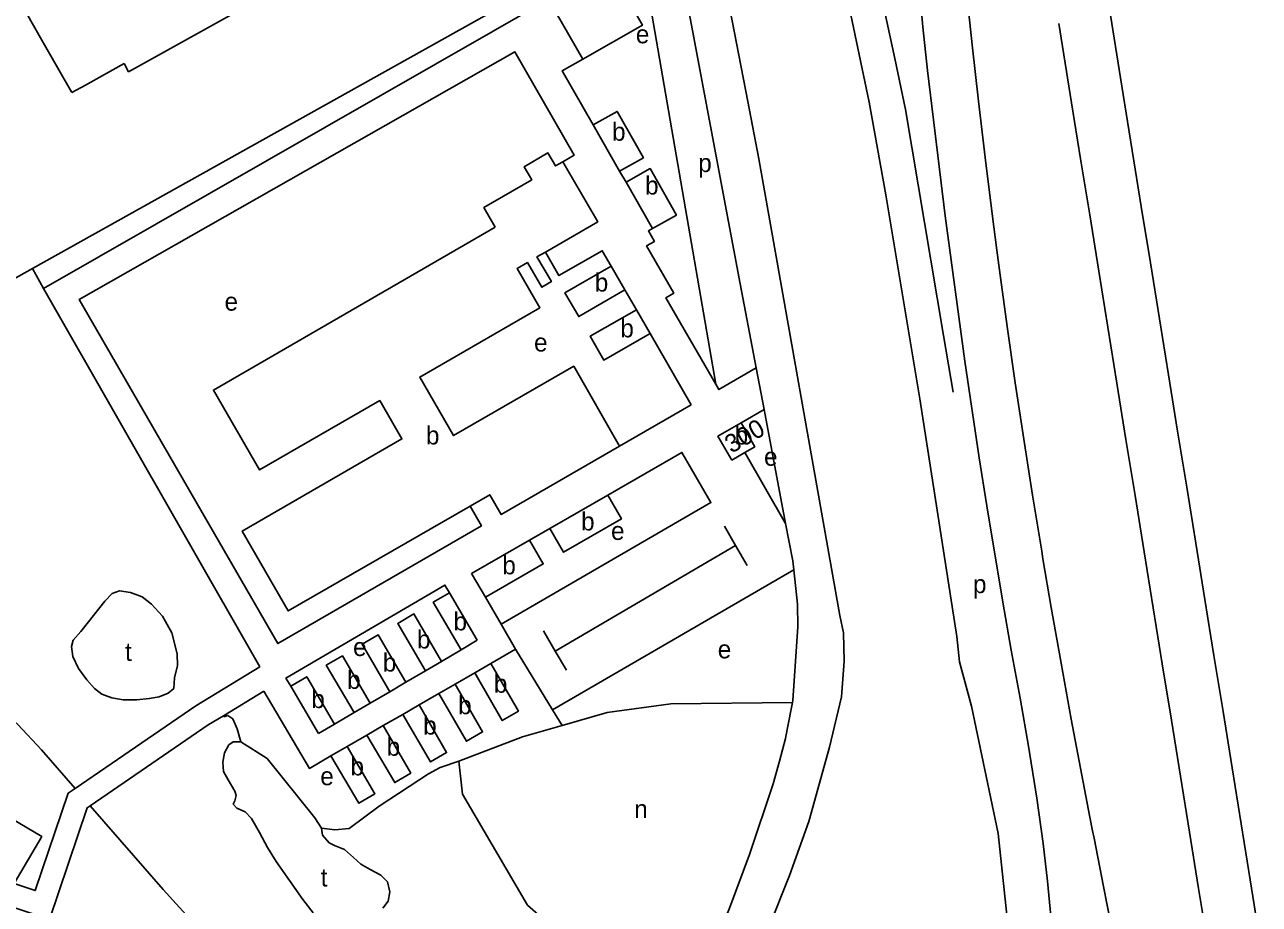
# Model space of a CAD drawing. Extents: x 155696 to 157795, y 382328 to 384028.
# Drawn here: x 157478.7 to 157750.1, y 382657.2 to 382850.6 of the extents above; entities that cross this region are included whole.
import ezdxf

# ---------------------------------------------------------------- set-up
doc = ezdxf.new("R2010")
doc.units = 0
for name, color, linetype in [('BLT_Basislijn', 7, 'Continuous'), ('BLT_Bebouwing', 7, 'Continuous'), ('BLT_Centroide', 7, 'Continuous'), ('BLT_Huisnummer', 7, 'Continuous')]:
    doc.layers.add(name, color=color, linetype=linetype)

msp = doc.modelspace()

# ---------------------------------------------------------------- linework, layer by layer
at = {"layer": 'BLT_Basislijn'}
for p, q in [((157637.68, 382833.72), (157627.76, 382885.04)), ((157620.61, 382875.41), (157635.97, 382793.64)), ((157613.37, 382871.36), (157480.36, 382797)), ((157630.65, 382771.56), (157613.37, 382871.36)), ((157593.85, 382856.25), (157482.81, 382792.61)), ((157489.02, 382835.69), (157482.7, 382846.69)), ((157640.12, 382821.11), (157637.68, 382833.72)), ((157609.47, 382818.39), (157610.92, 382816)), ((157480.36, 382797), (157468.95, 382790.62)), ((157482.81, 382792.61), (157480.36, 382797)), ((157635.97, 382793.64), (157639.54, 382775.14)), ((157482.81, 382792.61), (157530.37, 382709.42)), ((157613.18, 382787.94), (157610.64, 382792.29)), ((157625.22, 382767.05), (157616.18, 382782.7)), ((157641.27, 382765.98), (157639.54, 382775.14)), ((157609.49, 382757.96), (157625.22, 382767.05)), ((157636.18, 382763.04), (157641.27, 382765.98)), ((157645.99, 382740.93), (157641.27, 382765.98)), ((157645.99, 382740.93), (157637, 382756.53)), ((157589.68, 382737.27), (157594.15, 382739.84)), ((157632.54, 382740.35), (157634.99, 382736.09)), ((157647.55, 382732.71), (157645.99, 382740.93)), ((157595.34, 382712.88), (157634.99, 382736.09)), ((157634.99, 382736.09), (157637.53, 382731.68)), ((157594.73, 382699.99), (157647.76, 382730.73)), ((157647.55, 382732.71), (157647.76, 382730.73)), ((157583.42, 382718.79), (157579.97, 382724.72)), ((157586.61, 382713.29), (157583.42, 382718.79)), ((157592.75, 382717.32), (157595.34, 382712.88)), ((157574.63, 382713.19), (157570.35, 382710.62)), ((157581.17, 382710.14), (157586.61, 382713.29)), ((157594.73, 382699.99), (157586.61, 382713.29)), ((157595.34, 382712.88), (157597.77, 382708.66)), ((157566.8, 382708.55), (157562.5, 382706.02)), ((157573.31, 382705.59), (157577.61, 382708.07)), ((157531.27, 382704.1), (157522.35, 382698.66)), ((157558.96, 382703.95), (157554.65, 382701.42)), ((157565.4, 382701.03), (157569.74, 382703.53)), ((157647.47, 382701.6), (157646.33, 382695.63)), ((157522.35, 382698.66), (157522.5, 382698.45)), ((157551.12, 382699.34), (157546.8, 382696.8)), ((157557.46, 382696.49), (157561.85, 382698.97)), ((157596.85, 382696.53), (157594.73, 382699.99)), ((157549.55, 382691.93), (157553.92, 382694.41)), ((157489.73, 382682.66), (157482.33, 382691.14))]:
    msp.add_line(p, q, dxfattribs=at)
for points in [[(157695.61, 382638.95), (157694.81, 382653.47), (157692.74, 382672.8), (157686.86, 382700.8), (157684.2, 382710.55), (157683.61, 382716.06), (157675.47, 382768.37), (157668.04, 382813.21), (157664.37, 382833.62), (157659.36, 382857.38), (157649.44, 382904.48), (157648.3, 382911.67), (157646.15, 382926.65), (157644.29, 382940.39), (157642.39, 382954.51), (157640.58, 382970.08)], [(157500.55, 382842.07), (157501.52, 382840.28), (157548.2, 382866.27), (157552.51, 382858.39), (157578.68, 382872.96), (157611.59, 382891.3), (157607.18, 382899.1), (157606.48, 382900.41)], [(157665.34, 382864.95), (157670.03, 382843.22), (157672.32, 382831.96), (157676.54, 382807.1), (157680.73, 382782.26), (157682.82, 382769.85)], [(157685.66, 382858.66), (157686.98, 382846.23), (157688.37, 382833.81), (157689.84, 382821.4), (157691.39, 382809), (157692.42, 382801.01), (157693.01, 382796.61), (157694.71, 382784.23), (157696.49, 382771.86), (157698.35, 382759.5), (157700.28, 382747.16), (157702.29, 382734.82), (157702.57, 382733.18), (157704.38, 382722.5), (157706.55, 382710.19), (157708.79, 382697.9), (157711.11, 382685.62), (157712.91, 382676.34), (157713.5, 382673.35), (157713.82, 382671.74), (157715.91, 382661.08), (157718.29, 382648.81)], [(157479.42, 382854.06), (157478.75, 382853.69), (157482.7, 382846.69)], [(157675.71, 382854.97), (157676.19, 382850.13), (157677.22, 382840.56), (157681.08, 382808.57), (157685.38, 382776.61)], [(157750.15, 382650.2), (157748.15, 382662.54), (157746.16, 382674.88), (157744.16, 382687.22), (157742.17, 382699.56), (157740.17, 382711.9), (157738.17, 382724.24), (157736.18, 382736.58), (157734.18, 382748.92), (157732.19, 382761.26), (157730.19, 382773.6), (157728.2, 382785.94), (157726.2, 382798.28), (157724.2, 382810.61), (157722.21, 382822.95), (157720.21, 382835.29), (157718.22, 382847.63), (157717.39, 382852.74)], [(157706.04, 382850.9), (157706.87, 382845.8), (157708.86, 382833.46), (157710.86, 382821.12), (157712.85, 382808.78), (157714.85, 382796.44), (157716.84, 382784.1), (157718.84, 382771.76), (157720.83, 382759.42), (157722.83, 382747.08), (157724.83, 382734.74), (157726.82, 382722.4), (157728.82, 382710.06), (157730.81, 382697.72), (157732.81, 382685.38), (157734.8, 382673.04), (157736.8, 382660.7), (157738.8, 382648.36)], [(157576.6, 382744.76), (157579.11, 382740.41), (157534.33, 382714.54), (157490.67, 382790.22), (157586.47, 382844.64), (157599.46, 382821.91), (157597.02, 382820.49)], [(157492, 382837.34), (157496.19, 382839.66), (157500.55, 382842.07)], [(157603.66, 382828.58), (157596.88, 382840.48), (157601.39, 382843.06)], [(157489.02, 382835.69), (157492, 382837.34)], [(157658.3, 382702.79), (157658.88, 382710.65), (157658.69, 382716.86), (157657.89, 382720.68), (157640.12, 382821.11)], [(157630.65, 382771.56), (157619.66, 382790.59), (157621.39, 382791.6), (157615.43, 382801.97), (157617.15, 382802.96), (157615.82, 382805.27), (157616.72, 382805.79)], [(157607.62, 382797.51), (157605.65, 382800.93), (157596.14, 382795.47), (157593.19, 382800.63)], [(157685.38, 382776.61), (157688.54, 382755.39), (157690.2, 382744.84), (157693.75, 382723.63), (157695.56, 382713.05), (157697.53, 382702.49), (157699.43, 382691.95), (157701.25, 382680.51), (157702.62, 382670.6), (157703.58, 382662.25), (157704.81, 382649.21), (157705.69, 382638.41), (157706.58, 382616.86), (157707.1, 382578.78), (157707.57, 382562.58), (157707.42, 382553.95), (157706.77, 382536.96), (157706.7, 382531.12), (157706.96, 382523.63), (157708.31, 382508.29), (157709.47, 382499.41), (157715.31, 382458.25)], [(157630.65, 382771.56), (157631.32, 382770.39), (157639.54, 382775.14)], [(157606.87, 382747.17), (157623.19, 382756.58), (157629.55, 382745.53), (157583.42, 382718.79)], [(157647.76, 382730.73), (157648.58, 382723.16), (157648.66, 382718.22), (157647.55, 382701.99), (157647.47, 382701.6)], [(157537.15, 382705.15), (157536.11, 382706.94), (157571.07, 382727.39), (157572.05, 382725.7)], [(157530.37, 382709.42), (157516.32, 382700.83), (157489.73, 382682.66)], [(157468.52, 382704.51), (157477.18, 382696.72), (157482.33, 382691.14)], [(157546.01, 382689.85), (157541.26, 382687.07), (157531.27, 382704.1)], [(157647.47, 382701.6), (157620.76, 382701.28), (157606.75, 382699.34), (157596.85, 382696.53)], [(157658.3, 382702.79), (157655.66, 382691.78), (157651.12, 382675.41), (157646.84, 382663.5), (157642.2, 382651.97), (157639.41, 382646)], [(157522.35, 382698.66), (157519.03, 382696.63), (157493.04, 382678.87)], [(157526.19, 382692.91), (157525.42, 382695.8), (157524.41, 382697.97), (157523.36, 382698.75), (157522.5, 382698.45)], [(157596.85, 382696.53), (157588.1, 382694.05), (157574.16, 382688.65)], [(157646.33, 382695.63), (157645.95, 382693.64), (157644.61, 382688.69)], [(157526.19, 382692.91), (157524.54, 382692.95), (157523.57, 382692.26), (157522.6, 382690.47), (157522.2, 382688.44), (157522.4, 382686.42), (157523.38, 382684.56), (157524.9, 382682.07), (157525.15, 382681.09), (157524.87, 382679.94), (157524.54, 382679.18), (157525.31, 382678.3), (157527.15, 382677.5), (157528.51, 382676.07), (157530.26, 382672.96), (157532.02, 382669.7), (157533.98, 382666.58), (157536.9, 382662.43), (157539.82, 382658.23), (157542.08, 382655.33)], [(157543.94, 382673.94), (157542.48, 382676.22), (157531.95, 382689.28), (157526.19, 382692.91)], [(157574.16, 382688.65), (157570.05, 382687.29), (157567.45, 382685.85), (157556.6, 382678.74), (157550.02, 382673.86), (157546.88, 382673.54), (157543.94, 382673.94)], [(157574.16, 382688.65), (157574.97, 382681.44), (157589.2, 382657.01), (157592.26, 382654.4), (157625.14, 382635.25)], [(157644.61, 382688.69), (157643.25, 382683.68), (157638.03, 382668.18), (157633.66, 382656.31), (157626.02, 382637.64)], [(157489.73, 382682.66), (157488.21, 382681.62), (157480.97, 382660.23), (157476.33, 382661.8)], [(157493.04, 382678.87), (157492.41, 382678.44), (157484.1, 382653.89), (157473.74, 382657.4)], [(157519.12, 382649.36), (157509.1, 382660.44), (157493.04, 382678.87)], [(157476.33, 382661.8), (157482.4, 382672.1), (157472.34, 382678.06)], [(157557.43, 382656.36), (157558.57, 382657.91), (157558.97, 382659.93), (157558.43, 382662.1), (157557, 382663.61), (157554.62, 382664.87), (157552.57, 382666.03), (157550.98, 382667.52), (157549.01, 382669.27), (157546.8, 382670.09), (157545.59, 382670.74), (157544.13, 382672.37), (157543.94, 382673.94)]]:
    msp.add_lwpolyline(points, dxfattribs=at)
msp.add_lwpolyline([(157489.34, 382715.28), (157491, 382717.15), (157492.67, 382719.29), (157496.32, 382723.85), (157497.93, 382725.55), (157499.5, 382726.13), (157501.96, 382725.76), (157504.53, 382724.79), (157506.53, 382723.21), (157508.97, 382720.55), (157511, 382716.92), (157512.17, 382712.29), (157512.24, 382709.72), (157511.6, 382706.97), (157511.43, 382704.66), (157510.18, 382703.66), (157508.21, 382702.85), (157506.07, 382702.44), (157503.31, 382702.16), (157500.34, 382702.15), (157497.84, 382702.58), (157495.66, 382703.4), (157494.02, 382704.64), (157492.33, 382706.53), (157490.53, 382709.05), (157489.23, 382711.68), (157488.92, 382713.86)], close=True, dxfattribs=at)
at = {"layer": 'BLT_Bebouwing'}
for p, q in [((157601.39, 382843.06), (157593.85, 382856.25)), ((157609.47, 382818.39), (157603.66, 382828.58)), ((157616.72, 382805.79), (157610.92, 382816)), ((157610.64, 382792.29), (157607.62, 382797.51)), ((157613.18, 382787.94), (157616.18, 382782.7)), ((157637, 382756.53), (157634.13, 382754.88)), ((157594.15, 382739.84), (157606.87, 382747.17)), ((157576.94, 382729.94), (157589.68, 382737.27)), ((157579.97, 382724.72), (157576.94, 382729.94)), ((157572.05, 382725.7), (157578.18, 382715.27)), ((157578.18, 382715.27), (157574.63, 382713.19)), ((157570.35, 382710.62), (157566.8, 382708.55)), ((157577.61, 382708.07), (157581.17, 382710.14)), ((157562.5, 382706.02), (157558.96, 382703.95)), ((157543.26, 382694.72), (157537.15, 382705.15)), ((157569.74, 382703.53), (157573.31, 382705.59)), ((157554.65, 382701.42), (157551.12, 382699.34)), ((157561.85, 382698.97), (157565.4, 382701.03)), ((157546.8, 382696.8), (157543.26, 382694.72)), ((157553.92, 382694.41), (157557.46, 382696.49)), ((157546.01, 382689.85), (157549.55, 382691.93))]:
    msp.add_line(p, q, dxfattribs=at)
for points in [[(157593.85, 382856.25), (157607.02, 382863.74), (157614.49, 382850.51), (157601.39, 382843.06)], [(157603.66, 382828.58), (157608.91, 382831.56), (157614.71, 382821.37), (157609.47, 382818.39)], [(157597.02, 382820.49), (157595.4, 382819.56), (157593.71, 382822.42), (157588.5, 382819.37), (157590.17, 382816.52), (157579.66, 382810.41), (157582.15, 382806.11)], [(157593.19, 382800.63), (157604.67, 382807.28), (157597.02, 382820.49)], [(157610.92, 382816), (157616.17, 382818.98), (157621.96, 382808.77), (157616.72, 382805.79)], [(157582.15, 382806.11), (157520.17, 382770.26), (157530.33, 382752.72), (157556.74, 382767.97), (157561.62, 382759.52), (157526.49, 382739.28), (157536.6, 382721.72), (157576.6, 382744.76)], [(157609.49, 382757.96), (157599.38, 382775.5), (157572.96, 382760.27), (157565.55, 382773.12), (157591.95, 382788.38), (157586.96, 382797.03), (157589.21, 382798.33), (157592.38, 382792.88), (157594.49, 382794.12), (157591.3, 382799.54), (157593.19, 382800.63)], [(157607.62, 382797.51), (157597.47, 382791.64), (157600.48, 382786.42), (157610.64, 382792.29)], [(157616.18, 382782.7), (157606.01, 382776.87), (157603.01, 382782.11), (157613.18, 382787.94)], [(157634.13, 382754.88), (157631.11, 382760.12), (157636.18, 382763.04)], [(157636.18, 382763.04), (157639.2, 382757.8), (157637, 382756.53)], [(157576.6, 382744.76), (157580.94, 382747.25), (157583.44, 382742.91), (157609.49, 382757.96)], [(157606.87, 382747.17), (157609.88, 382741.95), (157597.17, 382734.61), (157594.15, 382739.84)], [(157589.68, 382737.27), (157592.68, 382732.04), (157579.97, 382724.72)], [(157574.63, 382713.19), (157568.51, 382723.62), (157572.05, 382725.7)], [(157566.8, 382708.55), (157560.7, 382718.98), (157564.24, 382721.06), (157570.35, 382710.62)], [(157558.96, 382703.95), (157552.84, 382714.38), (157556.38, 382716.46), (157562.5, 382706.02)], [(157551.12, 382699.34), (157544.97, 382709.75), (157548.51, 382711.83), (157554.65, 382701.42)], [(157581.17, 382710.14), (157587.24, 382699.68), (157583.68, 382697.61), (157577.61, 382708.07)], [(157537.15, 382705.15), (157540.69, 382707.23), (157546.8, 382696.8)], [(157573.31, 382705.59), (157579.35, 382695.11), (157575.79, 382693.06), (157569.74, 382703.53)], [(157565.4, 382701.03), (157571.45, 382690.55), (157567.9, 382688.5), (157561.85, 382698.97)], [(157557.46, 382696.49), (157563.57, 382686.06), (157560.03, 382683.98), (157553.92, 382694.41)], [(157549.55, 382691.93), (157555.69, 382681.52), (157552.15, 382679.43), (157546.01, 382689.85)]]:
    msp.add_lwpolyline(points, dxfattribs=at)

# ---------------------------------------------------------------- texts
at = {"layer": 'BLT_Centroide'}
for s, p in [('e', (157613.05, 382846.53)), ('b', (157607.82, 382825.11)), ('p', (157626.77, 382818.22)), ('b', (157615.08, 382813.27)), ('b', (157604.02, 382791.94)), ('e', (157522.61, 382787.74)), ('b', (157609.64, 382781.87)), ('e', (157590.67, 382778.76)), ('b', (157566.89, 382758.32)), ('b', (157634.78, 382758.32)), ('e', (157641.24, 382753.64)), ('b', (157601.01, 382739.4)), ('e', (157607.6, 382737.32)), ('b', (157583.69, 382729.76)), ('p', (157687.18, 382725.62)), ('b', (157572.96, 382717.42)), ('b', (157564.93, 382713.45)), ('t', (157500.74, 382710.72)), ('e', (157550.87, 382711.79)), ('e', (157631.06, 382711.28)), ('b', (157557.41, 382708.38)), ('b', (157549.55, 382704.57)), ('b', (157581.83, 382703.72)), ('b', (157541.69, 382700.34)), ('b', (157573.97, 382698.99)), ('b', (157566.28, 382694.51)), ('b', (157558.25, 382689.86)), ('b', (157550.31, 382685.54)), ('e', (157543.66, 382683.38)), ('n', (157612.69, 382676.14)), ('t', (157543.76, 382661.11))]:
    msp.add_text(s, height=4, dxfattribs=at).set_placement(p)
at = {"layer": 'BLT_Huisnummer'}
msp.add_text('300', height=4, rotation=29.7393, dxfattribs=at).set_placement((157634.07, 382756.26))

doc.saveas('drawing.dxf')
